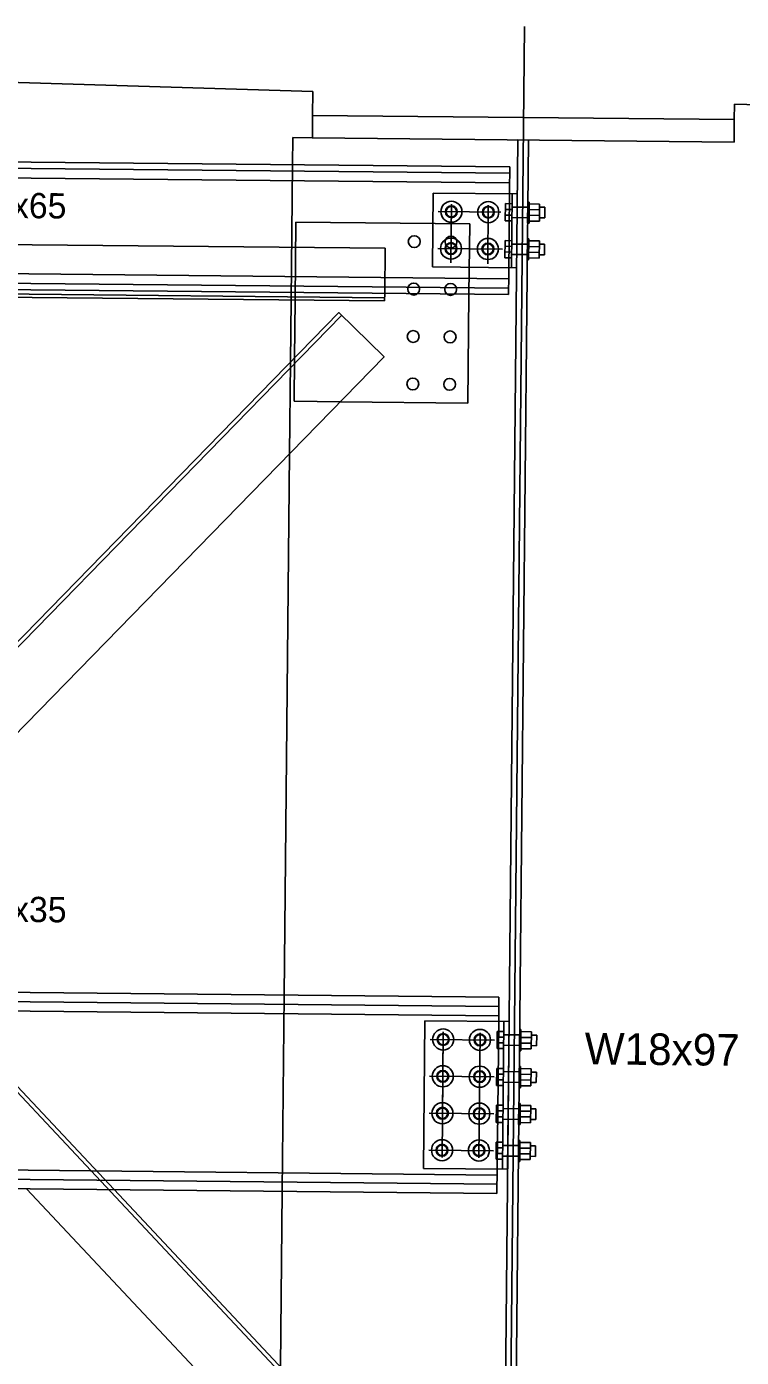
# Model space of a CAD drawing. Extents: x 632312 to 632885, y 378199 to 378534.
# Drawn here: x 632348.09 to 632353.74, y 378386.07 to 378396.59 of the extents above; entities that cross this region are included whole.
import ezdxf

# ---------------------------------------------------------------- set-up
doc = ezdxf.new("R2010")
doc.units = 0
for name, color, linetype in [('B_Boring', 7, 'Continuous'), ('B_Boring Annot', 7, 'Continuous'), ('R_Proposed Const Limits Cut', 7, 'Continuous'), ('R_Shade Removal', 7, 'Continuous'), ('R_Wall', 7, 'Continuous'), ('SHT_Dimensions', 7, 'Continuous')]:
    doc.layers.add(name, color=color, linetype=linetype)

msp = doc.modelspace()

# ---------------------------------------------------------------- linework, layer by layer
at = {"layer": 'B_Boring'}
for p, q in [((632350.191, 378395.714), (632350.189, 378395.499)), ((632350.347, 378395.712), (632350.191, 378395.714)), ((632351.908, 378395.482), (632340.867, 378395.592)), ((632351.907, 378395.432), (632340.866, 378395.541)), ((632351.906, 378395.294), (632351.908, 378395.482)), ((632351.301, 378395.275), (632351.296, 378394.692)), ((632351.968, 378395.269), (632351.301, 378395.275)), ((632351.921, 378394.686), (632351.926, 378395.269)), ((632351.874, 378395.192), (632351.872, 378395.056)), ((632351.925, 378395.146), (632351.873, 378395.147)), ((632351.926, 378395.191), (632351.874, 378395.192)), ((632351.926, 378395.191), (632351.924, 378395.056)), ((632352.051, 378395.206), (632352.049, 378395.039)), ((632352.051, 378395.206), (632352.061, 378395.205)), ((632352.061, 378395.205), (632352.06, 378395.039)), ((632352.061, 378395.19), (632352.144, 378395.189)), ((632352.061, 378395.145), (632352.144, 378395.144)), ((632352.144, 378395.189), (632352.143, 378395.054)), ((632352.144, 378395.163), (632352.186, 378395.163)), ((632352.186, 378395.163), (632352.185, 378395.079)), ((632350.216, 378395.047), (632350.216, 378395.047)), ((632351.924, 378395.056), (632351.872, 378395.056)), ((632351.925, 378395.101), (632351.873, 378395.101)), ((632352.049, 378395.039), (632352.06, 378395.039)), ((632352.06, 378395.1), (632352.144, 378395.099)), ((632352.06, 378395.054), (632352.143, 378395.054)), ((632352.143, 378395.08), (632352.185, 378395.079)), ((632351.871, 378394.9), (632351.869, 378394.765)), ((632351.922, 378394.854), (632351.87, 378394.855)), ((632351.923, 378394.899), (632351.871, 378394.9)), ((632351.923, 378394.899), (632351.921, 378394.764)), ((632352.048, 378394.914), (632352.046, 378394.747)), ((632352.048, 378394.914), (632352.058, 378394.914)), ((632352.058, 378394.914), (632352.057, 378394.747)), ((632352.058, 378394.898), (632352.142, 378394.897)), ((632352.058, 378394.853), (632352.141, 378394.852)), ((632352.142, 378394.897), (632352.14, 378394.762)), ((632352.141, 378394.871), (632352.183, 378394.871)), ((632352.183, 378394.871), (632352.182, 378394.788)), ((632351.921, 378394.764), (632351.869, 378394.765)), ((632351.922, 378394.809), (632351.87, 378394.81)), ((632352.046, 378394.747), (632352.057, 378394.747)), ((632352.057, 378394.808), (632352.141, 378394.807)), ((632352.057, 378394.763), (632352.14, 378394.762)), ((632352.14, 378394.788), (632352.182, 378394.788)), ((632351.898, 378394.524), (632340.857, 378394.634)), ((632351.296, 378394.692), (632351.962, 378394.686)), ((632351.899, 378394.627), (632351.898, 378394.474)), ((632351.898, 378394.474), (632340.857, 378394.583)), ((632346.377, 378394.468), (632350.918, 378394.423)), ((632350.178, 378394.43), (632350.174, 378393.94)), ((632350.918, 378394.423), (632350.919, 378394.483)), ((632351.577, 378393.616), (632351.585, 378394.477)), ((632350.567, 378393.626), (632351.577, 378393.616)), ((632350.166, 378393.217), (632350.124, 378388.936)), ((632351.822, 378388.92), (632340.822, 378389.029)), ((632351.821, 378388.847), (632340.821, 378388.956)), ((632351.82, 378388.728), (632351.822, 378388.92)), ((632351.236, 378388.734), (632351.225, 378387.567)), ((632351.903, 378388.727), (632351.236, 378388.734)), ((632351.85, 378387.561), (632351.861, 378388.727)), ((632351.809, 378388.65), (632351.807, 378388.514)), ((632351.861, 378388.649), (632351.809, 378388.65)), ((632351.986, 378388.664), (632351.996, 378388.664)), ((632351.996, 378388.664), (632351.995, 378388.497)), ((632351.996, 378388.648), (632352.079, 378388.647)), ((632352.079, 378388.647), (632352.078, 378388.512)), ((632352.079, 378388.621), (632352.121, 378388.621)), ((632352.121, 378388.621), (632352.12, 378388.537)), ((632351.859, 378388.514), (632351.807, 378388.514)), ((632351.86, 378388.604), (632351.808, 378388.605)), ((632351.86, 378388.559), (632351.808, 378388.56)), ((632351.995, 378388.558), (632352.078, 378388.557)), ((632351.995, 378388.513), (632352.078, 378388.512)), ((632351.996, 378388.603), (632352.079, 378388.602)), ((632352.078, 378388.538), (632352.12, 378388.537)), ((632351.984, 378388.497), (632351.995, 378388.497)), ((632351.806, 378388.358), (632351.804, 378388.223)), ((632351.857, 378388.313), (632351.805, 378388.313)), ((632351.858, 378388.358), (632351.806, 378388.358)), ((632351.983, 378388.372), (632351.993, 378388.372)), ((632351.993, 378388.372), (632351.992, 378388.205)), ((632351.993, 378388.356), (632352.076, 378388.355)), ((632351.993, 378388.311), (632352.076, 378388.31)), ((632352.076, 378388.355), (632352.075, 378388.22)), ((632352.076, 378388.329), (632352.118, 378388.329)), ((632352.118, 378388.329), (632352.117, 378388.246)), ((632351.856, 378388.222), (632351.804, 378388.223)), ((632351.857, 378388.267), (632351.805, 378388.268)), ((632351.981, 378388.205), (632351.992, 378388.205)), ((632351.992, 378388.266), (632352.076, 378388.265)), ((632351.992, 378388.221), (632352.075, 378388.22)), ((632352.075, 378388.246), (632352.117, 378388.246)), ((632351.803, 378388.067), (632351.801, 378387.931)), ((632351.854, 378388.021), (632351.802, 378388.021)), ((632351.854, 378387.976), (632351.802, 378387.976)), ((632351.855, 378388.066), (632351.803, 378388.067)), ((632351.98, 378388.08), (632351.99, 378388.08)), ((632351.99, 378388.08), (632351.989, 378387.914)), ((632351.99, 378388.065), (632352.074, 378388.064)), ((632351.99, 378388.02), (632352.073, 378388.019)), ((632352.074, 378388.064), (632352.072, 378387.928)), ((632352.073, 378388.038), (632352.115, 378388.037)), ((632352.115, 378388.037), (632352.114, 378387.954)), ((632351.853, 378387.931), (632351.801, 378387.931)), ((632351.978, 378387.914), (632351.989, 378387.914)), ((632351.989, 378387.974), (632352.073, 378387.974)), ((632351.989, 378387.929), (632352.072, 378387.928)), ((632352.072, 378387.954), (632352.114, 378387.954)), ((632351.8, 378387.775), (632351.799, 378387.639)), ((632351.852, 378387.774), (632351.8, 378387.775)), ((632351.977, 378387.789), (632351.988, 378387.789)), ((632351.988, 378387.789), (632351.986, 378387.622)), ((632351.987, 378387.773), (632352.071, 378387.772)), ((632352.071, 378387.772), (632352.069, 378387.637)), ((632351.851, 378387.729), (632351.799, 378387.73)), ((632351.851, 378387.684), (632351.799, 378387.685)), ((632351.986, 378387.683), (632352.07, 378387.682)), ((632351.987, 378387.728), (632352.07, 378387.727)), ((632352.07, 378387.746), (632352.112, 378387.746)), ((632352.07, 378387.663), (632352.111, 378387.662)), ((632352.112, 378387.746), (632352.111, 378387.662)), ((632351.225, 378387.567), (632351.891, 378387.56)), ((632351.851, 378387.639), (632351.799, 378387.639)), ((632351.806, 378387.37), (632351.808, 378387.561)), ((632351.975, 378387.622), (632351.986, 378387.622)), ((632351.986, 378387.638), (632352.069, 378387.637)), ((632351.806, 378387.37), (632340.807, 378387.479)), ((632351.807, 378387.442), (632340.808, 378387.551)), ((632350.108, 378387.386), (632350.095, 378385.998))]:
    msp.add_line(p, q, dxfattribs=at)
for points in [[(632353.681, 378395.679), (632353.682, 378395.856), (632350.349, 378395.889), (632350.347, 378395.712)], [(632351.936, 378383.696), (632351.853, 378383.697), (632351.972, 378395.696), (632352.056, 378395.695)]]:
    msp.add_lwpolyline(points, close=True, dxfattribs=at)
for points in [[(632350.21, 378394.43), (632350.205, 378393.972)], [(632347.136, 378390.114), (632350.914, 378393.982), (632350.556, 378394.331), (632347.131, 378390.825)], [(632350.462, 378384.876), (632348.087, 378387.407)], [(632348.779, 378387.4), (632350.826, 378385.218)]]:
    msp.add_lwpolyline(points, dxfattribs=at)
for centre in [(632351.446, 378395.128), (632351.738, 378395.125), (632351.152, 378394.892), (632351.443, 378394.889), (632351.443, 378394.837), (632351.735, 378394.834), (632351.148, 378394.517), (632351.44, 378394.514), (632351.144, 378394.142), (632351.436, 378394.139), (632351.141, 378393.767), (632351.432, 378393.764), (632351.381, 378388.586), (632351.672, 378388.583), (632351.378, 378388.295), (632351.67, 378388.292), (632351.375, 378388.003), (632351.667, 378388), (632351.372, 378387.711), (632351.664, 378387.709)]:
    msp.add_circle(centre, 0.0469, dxfattribs=at)
at = {"layer": 'B_Boring Annot'}
for p, q in [((632346.394, 378396.197), (632350.351, 378396.079)), ((632350.351, 378396.079), (632350.349, 378395.889)), ((632353.682, 378395.856), (632353.684, 378395.979)), ((632353.684, 378395.979), (632355.238, 378395.932)), ((632350.349, 378395.889), (632353.682, 378395.856))]:
    msp.add_line(p, q, dxfattribs=at)
at = {"layer": 'R_Proposed Const Limits Cut'}
for p, q in [((632351.906, 378395.357), (632340.865, 378395.467)), ((632350.189, 378395.499), (632350.178, 378394.43)), ((632351.899, 378394.627), (632351.906, 378395.294)), ((632351.925, 378395.165), (632352.05, 378395.164)), ((632350.21, 378394.43), (632350.216, 378395.047)), ((632351.591, 378395.033), (632350.216, 378395.047)), ((632351.591, 378395.033), (632351.585, 378394.477)), ((632351.925, 378395.082), (632352.05, 378395.081)), ((632350.922, 378394.84), (632341.839, 378394.93)), ((632350.919, 378394.483), (632350.922, 378394.84)), ((632351.923, 378394.873), (632352.048, 378394.872)), ((632351.899, 378394.599), (632340.858, 378394.708)), ((632351.922, 378394.79), (632352.047, 378394.789)), ((632350.918, 378394.449), (632341.835, 378394.539)), ((632342.173, 378394.393), (632350.804, 378385.197)), ((632350.578, 378394.309), (632341.766, 378385.287)), ((632350.205, 378393.972), (632350.202, 378393.63)), ((632350.166, 378393.217), (632350.174, 378393.94)), ((632350.567, 378393.626), (632350.202, 378393.63)), ((632347.31, 378388.964), (632348.779, 378387.4)), ((632350.108, 378387.386), (632350.124, 378388.936)), ((632351.82, 378388.774), (632340.821, 378388.883)), ((632351.82, 378388.728), (632351.808, 378387.561)), ((632351.86, 378388.623), (632351.985, 378388.622)), ((632351.86, 378388.54), (632351.985, 378388.539)), ((632351.857, 378388.332), (632351.982, 378388.33)), ((632351.857, 378388.248), (632351.982, 378388.247)), ((632351.855, 378388.04), (632351.98, 378388.039)), ((632351.854, 378387.957), (632351.979, 378387.955)), ((632351.851, 378387.665), (632351.976, 378387.664)), ((632351.852, 378387.748), (632351.977, 378387.747)), ((632351.808, 378387.515), (632340.808, 378387.625))]:
    msp.add_line(p, q, dxfattribs=at)
for centre, radius in [((632351.446, 378395.128), 0.0833), ((632351.446, 378395.128), 0.0417), ((632351.738, 378395.125), 0.0833), ((632351.738, 378395.125), 0.0417), ((632351.443, 378394.837), 0.0833), ((632351.735, 378394.834), 0.0833), ((632351.443, 378394.837), 0.0417), ((632351.735, 378394.834), 0.0417), ((632351.381, 378388.586), 0.0833), ((632351.381, 378388.586), 0.0417), ((632351.672, 378388.583), 0.0833), ((632351.672, 378388.583), 0.0417), ((632351.378, 378388.295), 0.0833), ((632351.378, 378388.295), 0.0417), ((632351.67, 378388.292), 0.0833), ((632351.67, 378388.292), 0.0417), ((632351.375, 378388.003), 0.0833), ((632351.667, 378388), 0.0833), ((632351.375, 378388.003), 0.0417), ((632351.667, 378388), 0.0417), ((632351.372, 378387.711), 0.0833), ((632351.664, 378387.709), 0.0833), ((632351.372, 378387.711), 0.0417), ((632351.664, 378387.709), 0.0417)]:
    msp.add_circle(centre, radius, dxfattribs=at)
at = {"layer": 'R_Shade Removal'}
msp.add_line((632351.883, 378382.519), (632352.023, 378396.591), dxfattribs=at)
at = {"layer": 'R_Wall'}
for p, q in [((632351.342, 378395.129), (632351.836, 378395.124)), ((632351.446, 378395.189), (632351.442, 378394.724)), ((632351.738, 378395.179), (632351.733, 378394.716)), ((632351.339, 378394.838), (632351.849, 378394.833)), ((632351.381, 378388.647), (632351.372, 378387.654)), ((632351.673, 378388.638), (632351.663, 378387.652)), ((632351.277, 378388.587), (632351.786, 378388.582)), ((632351.274, 378388.296), (632351.784, 378388.291)), ((632351.271, 378388.004), (632351.781, 378387.999)), ((632351.268, 378387.712), (632351.778, 378387.707))]:
    msp.add_line(p, q, dxfattribs=at)
at = {"layer": 'SHT_Dimensions'}
for p, q in [((632351.903, 378388.727), (632351.891, 378387.56)), ((632351.381, 378388.647), (632351.375, 378387.957)), ((632351.861, 378388.649), (632351.859, 378388.514)), ((632351.858, 378388.358), (632351.856, 378388.222)), ((632351.855, 378388.066), (632351.853, 378387.931)), ((632351.98, 378388.08), (632351.978, 378387.914)), ((632351.852, 378387.774), (632351.851, 378387.639))]:
    msp.add_line(p, q, dxfattribs=at)

# ---------------------------------------------------------------- texts
for s, height, p in [('W12x65', 0.2, (632347.42, 378395.084)), ('W18x35', 0.2, (632347.421, 378389.521)), ('W18x97', 0.25, (632352.499, 378388.39))]:
    msp.add_text(s, height=height, rotation=359.4304, dxfattribs=at).set_placement(p)

doc.saveas('drawing.dxf')
